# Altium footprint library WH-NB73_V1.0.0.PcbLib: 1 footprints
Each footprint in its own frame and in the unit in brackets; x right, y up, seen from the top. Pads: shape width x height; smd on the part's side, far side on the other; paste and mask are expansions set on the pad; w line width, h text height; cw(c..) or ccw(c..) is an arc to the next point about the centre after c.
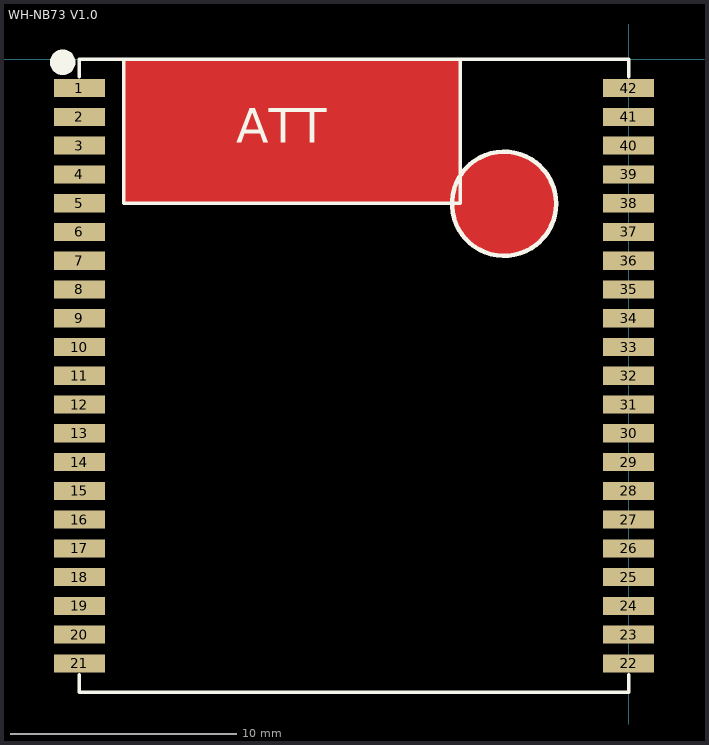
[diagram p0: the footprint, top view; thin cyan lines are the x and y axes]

## WH-NB73 V1.0 [mm]
pads (42):
  rect 2.25x0.8 smd: 1(-24.25,-1.27) 2(-24.25,-2.54) 3(-24.25,-3.81) 4(-24.25,-5.08) 5(-24.25,-6.35) 6(-24.25,-7.62) 7(-24.25,-8.89) 8(-24.25,-10.16) 9(-24.25,-11.43) 10(-24.25,-12.7) 11(-24.25,-13.97) 12(-24.25,-15.24) 13(-24.25,-16.51) 14(-24.25,-17.78) 15(-24.25,-19.05) 16(-24.25,-20.32) 17(-24.25,-21.59) 18(-24.25,-22.86) 19(-24.25,-24.13) 20(-24.25,-25.4) 21(-24.25,-26.67) 22(0,-26.67) 23(0,-25.4) 24(0,-24.13) 25(0,-22.86) 26(0,-21.59) 27(0,-20.32) 28(0,-19.05) 29(0,-17.78) 30(0,-16.51) 31(0,-15.24) 32(0,-13.97) 33(0,-12.7) 34(0,-11.43) 35(0,-10.16) 36(0,-8.89) 37(0,-7.62) 38(0,-6.35) 39(0,-5.08) 40(0,-3.81) 41(0,-2.54) 42(0,-1.27)
Top Layer:
  pour cut-out: -3.189,-6.375 -3.233,-5.923 -3.365,-5.489 -3.579,-5.088 -3.867,-4.737 -4.218,-4.449 -4.619,-4.235 -5.053,-4.103 -5.505,-4.059 -5.505,-4.07 -5.55,-4.059 -5.99,-4.102 -6.414,-4.231 -6.804,-4.439 -7.146,-4.72 -7.427,-5.062 -7.635,-5.452 -7.764,-5.876 -7.807,-6.316 -7.796,-6.316 -7.807,-6.37 -7.762,-6.825 -7.63,-7.262 -7.414,-7.665 -7.124,-8.018 -6.771,-8.308 -6.368,-8.524 -5.931,-8.656 -5.476,-8.701 -5.476,-8.69 -5.46,-8.701 -5.017,-8.657 -4.591,-8.528 -4.198,-8.318 -3.854,-8.036 -3.572,-7.692 -3.362,-7.299 -3.233,-6.873 -3.189,-6.43 -3.2,-6.43
  pour cut-out: -22.285,-6.35 -22.285,0 -7.426,0 -7.426,-6.35
Top Overlay:
  circle w0.2: c-5.5,-6.375 r2.3
  circle w0.559: c-24.987,-0.127 r0.284
  lines w0.152: -24.25,-27.178 -24.25,-27.94 0,-27.94 0,-27.178 ; -24.25,-0.762 -24.25,0 0,0 0,-0.762 ; -22.285,-2.54 -22.285,-6.35 -10.412,-6.35 -7.426,-6.35 -7.426,-5.08 -7.426,0 ; -22.285,-2.508 -22.285,0
  text "ATT" at -17.332,-3.683 h1.52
